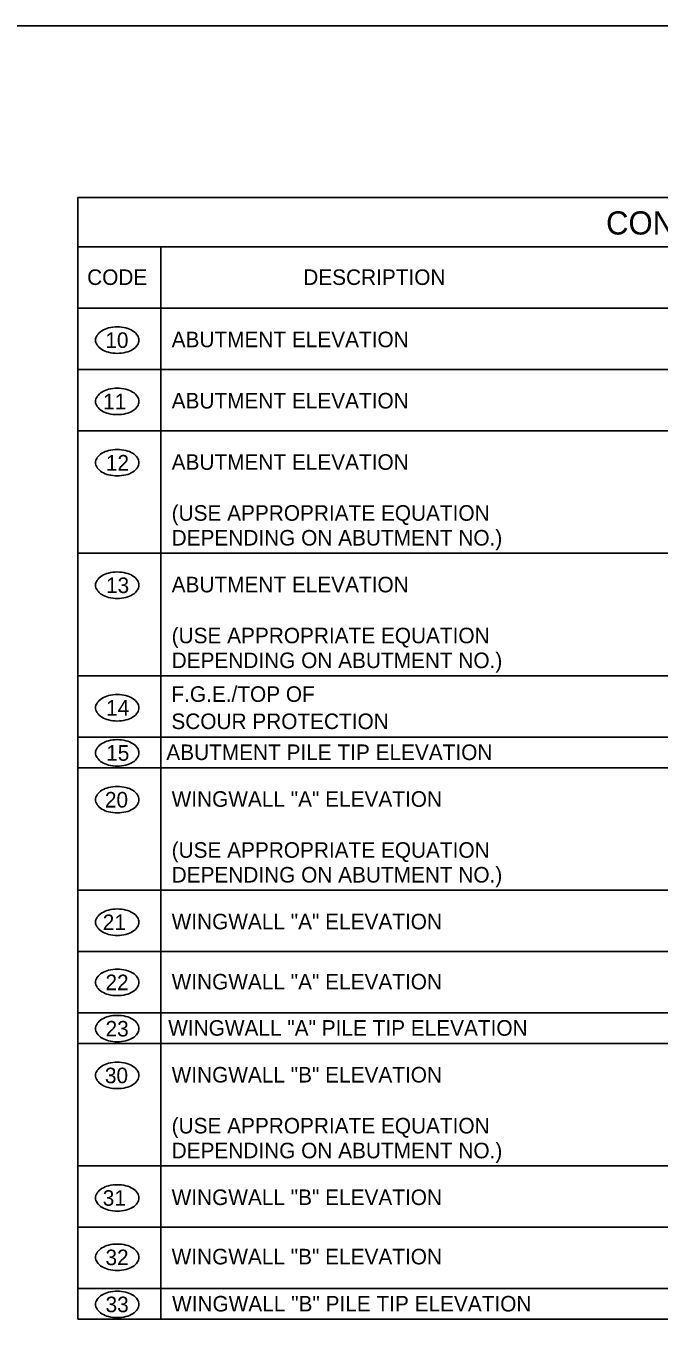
# Model space of a CAD drawing. Extents: x -5022 to -159, y 1126 to 7226.
# Drawn here: x -839.3 to -717.2, y 2049.8 to 2299.1 of the extents above; entities that cross this region are included whole.
import ezdxf

# ---------------------------------------------------------------- set-up
doc = ezdxf.new("R2010")
doc.units = 0
for name, color, linetype in [('2', 7, 'Continuous'), ('3', 7, 'Continuous'), ('5', 7, 'Continuous')]:
    doc.layers.add(name, color=color, linetype=linetype)

msp = doc.modelspace()

# ---------------------------------------------------------------- linework, layer by layer
at = {"layer": '2'}
msp.add_line((-491.13, 2299.14), (-1277.13, 2299.14), dxfattribs=at)
for centre, radius, start, end in [((-824.22, 2238.55), 1.61, 145.8704, 180), ((-822.99, 2237.72), 3.1, 121.4296, 145.8704), ((-822.18, 2236.39), 4.65, 104.2049, 121.4296), ((-821.65, 2234.29), 6.82, 90, 104.2049), ((-821.65, 2234.29), 6.82, 75.7951, 90), ((-821.11, 2236.39), 4.65, 58.5704, 75.7951), ((-820.3, 2237.72), 3.1, 34.1296, 58.5704), ((-819.07, 2238.55), 1.61, 0, 34.1296), ((-824.22, 2238.55), 1.61, 180, 214.1296), ((-822.99, 2239.39), 3.1, 214.1296, 238.5704), ((-822.18, 2240.72), 4.65, 238.5704, 255.7951), ((-821.11, 2240.72), 4.65, 284.2049, 301.4296), ((-820.3, 2239.39), 3.1, 301.4296, 325.8704), ((-819.07, 2238.55), 1.61, 325.8704, 0), ((-821.65, 2242.82), 6.82, 255.7951, 270), ((-821.65, 2242.82), 6.82, 270, 284.2049), ((-822.18, 2224.58), 4.65, 104.2049, 121.4296), ((-821.65, 2222.48), 6.82, 90, 104.2049), ((-821.65, 2222.48), 6.82, 75.7951, 90), ((-821.11, 2224.58), 4.65, 58.5704, 75.7951), ((-824.22, 2226.74), 1.61, 145.8704, 180), ((-824.22, 2226.74), 1.61, 180, 214.1296), ((-822.99, 2225.91), 3.1, 121.4296, 145.8704), ((-820.3, 2225.91), 3.1, 34.1296, 58.5704), ((-819.07, 2226.74), 1.61, 0, 34.1296), ((-819.07, 2226.74), 1.61, 325.8704, 0), ((-822.99, 2227.58), 3.1, 214.1296, 238.5704), ((-822.18, 2228.9), 4.65, 238.5704, 255.7951), ((-821.65, 2231.01), 6.82, 255.7951, 270), ((-821.65, 2231.01), 6.82, 270, 284.2049), ((-821.11, 2228.9), 4.65, 284.2049, 301.4296), ((-820.3, 2227.58), 3.1, 301.4296, 325.8704), ((-822.99, 2214.1), 3.1, 121.4296, 145.8704), ((-822.18, 2212.77), 4.65, 104.2049, 121.4296), ((-821.65, 2210.66), 6.82, 90, 104.2049), ((-821.65, 2210.66), 6.82, 75.7951, 90), ((-821.11, 2212.77), 4.65, 58.5704, 75.7951), ((-820.3, 2214.1), 3.1, 34.1296, 58.5704), ((-824.22, 2214.93), 1.61, 145.8704, 180), ((-824.22, 2214.93), 1.61, 180, 214.1296), ((-822.99, 2215.77), 3.1, 214.1296, 238.5704), ((-820.3, 2215.77), 3.1, 301.4296, 325.8704), ((-819.07, 2214.93), 1.61, 0, 34.1296), ((-819.07, 2214.93), 1.61, 325.8704, 0), ((-822.18, 2217.09), 4.65, 238.5704, 255.7951), ((-821.65, 2219.2), 6.82, 255.7951, 270), ((-821.65, 2219.2), 6.82, 270, 284.2049), ((-821.11, 2217.09), 4.65, 284.2049, 301.4296), ((-821.65, 2187.04), 6.82, 90, 104.2049), ((-821.65, 2187.04), 6.82, 75.7951, 90), ((-824.22, 2191.31), 1.61, 145.8704, 180), ((-822.99, 2190.48), 3.1, 121.4296, 145.8704), ((-822.18, 2189.15), 4.65, 104.2049, 121.4296), ((-821.11, 2189.15), 4.65, 58.5704, 75.7951), ((-820.3, 2190.48), 3.1, 34.1296, 58.5704), ((-819.07, 2191.31), 1.61, 0, 34.1296), ((-824.22, 2191.31), 1.61, 180, 214.1296), ((-822.99, 2192.14), 3.1, 214.1296, 238.5704), ((-822.18, 2193.47), 4.65, 238.5704, 255.7951), ((-821.65, 2195.58), 6.82, 255.7951, 270), ((-821.65, 2195.58), 6.82, 270, 284.2049), ((-821.11, 2193.47), 4.65, 284.2049, 301.4296), ((-820.3, 2192.14), 3.1, 301.4296, 325.8704), ((-819.07, 2191.31), 1.61, 325.8704, 0), ((-822.99, 2166.85), 3.1, 121.4296, 145.8704), ((-822.18, 2165.52), 4.65, 104.2049, 121.4296), ((-821.65, 2163.42), 6.82, 90, 104.2049), ((-821.65, 2163.42), 6.82, 75.7951, 90), ((-821.11, 2165.52), 4.65, 58.5704, 75.7951), ((-820.3, 2166.85), 3.1, 34.1296, 58.5704), ((-824.22, 2167.69), 1.61, 145.8704, 180), ((-824.22, 2167.69), 1.61, 180, 214.1296), ((-822.99, 2168.52), 3.1, 214.1296, 238.5704), ((-820.3, 2168.52), 3.1, 301.4296, 325.8704), ((-819.07, 2167.69), 1.61, 0, 34.1296), ((-819.07, 2167.69), 1.61, 325.8704, 0), ((-822.18, 2169.85), 4.65, 238.5704, 255.7951), ((-821.65, 2171.95), 6.82, 255.7951, 270), ((-821.65, 2171.95), 6.82, 270, 284.2049), ((-821.11, 2169.85), 4.65, 284.2049, 301.4296), ((-821.65, 2154.72), 6.82, 90, 104.2049), ((-821.65, 2154.72), 6.82, 75.7951, 90), ((-824.22, 2158.99), 1.61, 145.8704, 180), ((-824.22, 2158.99), 1.61, 180, 214.1296), ((-822.99, 2158.15), 3.1, 121.4296, 145.8704), ((-822.18, 2156.82), 4.65, 104.2049, 121.4296), ((-821.11, 2156.82), 4.65, 58.5704, 75.7951), ((-820.3, 2158.15), 3.1, 34.1296, 58.5704), ((-819.07, 2158.99), 1.61, 0, 34.1296), ((-819.07, 2158.99), 1.61, 325.8704, 0), ((-822.99, 2159.82), 3.1, 214.1296, 238.5704), ((-822.18, 2161.15), 4.65, 238.5704, 255.7951), ((-821.65, 2163.25), 6.82, 255.7951, 270), ((-821.65, 2163.25), 6.82, 270, 284.2049), ((-821.11, 2161.15), 4.65, 284.2049, 301.4296), ((-820.3, 2159.82), 3.1, 301.4296, 325.8704), ((-822.99, 2149.14), 3.1, 121.4296, 145.8704), ((-822.18, 2147.81), 4.65, 104.2049, 121.4296), ((-821.65, 2145.7), 6.82, 90, 104.2049), ((-821.65, 2145.7), 6.82, 75.7951, 90), ((-821.11, 2147.81), 4.65, 58.5704, 75.7951), ((-820.3, 2149.14), 3.1, 34.1296, 58.5704), ((-824.22, 2149.97), 1.61, 145.8704, 180), ((-824.22, 2149.97), 1.61, 180, 214.1296), ((-822.99, 2150.8), 3.1, 214.1296, 238.5704), ((-820.3, 2150.8), 3.1, 301.4296, 325.8704), ((-819.07, 2149.97), 1.61, 0, 34.1296), ((-819.07, 2149.97), 1.61, 325.8704, 0), ((-822.18, 2152.13), 4.65, 238.5704, 255.7951), ((-821.65, 2154.24), 6.82, 255.7951, 270), ((-821.65, 2154.24), 6.82, 270, 284.2049), ((-821.11, 2152.13), 4.65, 284.2049, 301.4296), ((-824.22, 2126.35), 1.61, 145.8704, 180), ((-822.99, 2125.51), 3.1, 121.4296, 145.8704), ((-822.18, 2124.18), 4.65, 104.2049, 121.4296), ((-821.65, 2122.08), 6.82, 90, 104.2049), ((-821.65, 2122.08), 6.82, 75.7951, 90), ((-821.11, 2124.18), 4.65, 58.5704, 75.7951), ((-820.3, 2125.51), 3.1, 34.1296, 58.5704), ((-819.07, 2126.35), 1.61, 0, 34.1296), ((-824.22, 2126.35), 1.61, 180, 214.1296), ((-822.99, 2127.18), 3.1, 214.1296, 238.5704), ((-822.18, 2128.51), 4.65, 238.5704, 255.7951), ((-821.11, 2128.51), 4.65, 284.2049, 301.4296), ((-820.3, 2127.18), 3.1, 301.4296, 325.8704), ((-819.07, 2126.35), 1.61, 325.8704, 0), ((-821.65, 2130.61), 6.82, 255.7951, 270), ((-821.65, 2130.61), 6.82, 270, 284.2049), ((-822.99, 2113.92), 3.1, 121.4296, 145.8704), ((-822.18, 2112.59), 4.65, 104.2049, 121.4296), ((-821.65, 2110.49), 6.82, 90, 104.2049), ((-821.65, 2110.49), 6.82, 75.7951, 90), ((-821.11, 2112.59), 4.65, 58.5704, 75.7951), ((-820.3, 2113.92), 3.1, 34.1296, 58.5704), ((-824.22, 2114.76), 1.61, 145.8704, 180), ((-824.22, 2114.76), 1.61, 180, 214.1296), ((-819.07, 2114.76), 1.61, 0, 34.1296), ((-819.07, 2114.76), 1.61, 325.8704, 0), ((-822.99, 2115.59), 3.1, 214.1296, 238.5704), ((-822.18, 2116.92), 4.65, 238.5704, 255.7951), ((-821.65, 2119.02), 6.82, 255.7951, 270), ((-821.65, 2119.02), 6.82, 270, 284.2049), ((-821.11, 2116.92), 4.65, 284.2049, 301.4296), ((-820.3, 2115.59), 3.1, 301.4296, 325.8704), ((-824.22, 2105.83), 1.61, 145.8704, 180), ((-822.99, 2105), 3.1, 121.4296, 145.8704), ((-822.18, 2103.67), 4.65, 104.2049, 121.4296), ((-821.65, 2101.57), 6.82, 90, 104.2049), ((-821.65, 2101.57), 6.82, 75.7951, 90), ((-821.11, 2103.67), 4.65, 58.5704, 75.7951), ((-820.3, 2105), 3.1, 34.1296, 58.5704), ((-819.07, 2105.83), 1.61, 0, 34.1296), ((-824.22, 2105.83), 1.61, 180, 214.1296), ((-822.99, 2106.67), 3.1, 214.1296, 238.5704), ((-820.3, 2106.67), 3.1, 301.4296, 325.8704), ((-819.07, 2105.83), 1.61, 325.8704, 0), ((-822.18, 2108), 4.65, 238.5704, 255.7951), ((-821.65, 2110.1), 6.82, 255.7951, 270), ((-821.65, 2110.1), 6.82, 270, 284.2049), ((-821.11, 2108), 4.65, 284.2049, 301.4296), ((-822.18, 2094.66), 4.65, 104.2049, 121.4296), ((-821.65, 2092.55), 6.82, 90, 104.2049), ((-821.65, 2092.55), 6.82, 75.7951, 90), ((-821.11, 2094.66), 4.65, 58.5704, 75.7951), ((-824.22, 2096.82), 1.61, 145.8704, 180), ((-824.22, 2096.82), 1.61, 180, 214.1296), ((-822.99, 2095.98), 3.1, 121.4296, 145.8704), ((-820.3, 2095.98), 3.1, 34.1296, 58.5704), ((-819.07, 2096.82), 1.61, 0, 34.1296), ((-819.07, 2096.82), 1.61, 325.8704, 0), ((-822.99, 2097.65), 3.1, 214.1296, 238.5704), ((-822.18, 2098.98), 4.65, 238.5704, 255.7951), ((-821.65, 2101.09), 6.82, 255.7951, 270), ((-821.65, 2101.09), 6.82, 270, 284.2049), ((-821.11, 2098.98), 4.65, 284.2049, 301.4296), ((-820.3, 2097.65), 3.1, 301.4296, 325.8704), ((-822.99, 2072.36), 3.1, 121.4296, 145.8704), ((-822.18, 2071.03), 4.65, 104.2049, 121.4296), ((-821.65, 2068.93), 6.82, 90, 104.2049), ((-821.65, 2068.93), 6.82, 75.7951, 90), ((-821.11, 2071.03), 4.65, 58.5704, 75.7951), ((-820.3, 2072.36), 3.1, 34.1296, 58.5704), ((-824.22, 2073.2), 1.61, 145.8704, 180), ((-824.22, 2073.2), 1.61, 180, 214.1296), ((-822.99, 2074.03), 3.1, 214.1296, 238.5704), ((-820.3, 2074.03), 3.1, 301.4296, 325.8704), ((-819.07, 2073.2), 1.61, 0, 34.1296), ((-819.07, 2073.2), 1.61, 325.8704, 0), ((-822.18, 2075.36), 4.65, 238.5704, 255.7951), ((-821.65, 2077.46), 6.82, 255.7951, 270), ((-821.65, 2077.46), 6.82, 270, 284.2049), ((-821.11, 2075.36), 4.65, 284.2049, 301.4296), ((-821.65, 2057.49), 6.82, 90, 104.2049), ((-821.65, 2057.49), 6.82, 75.7951, 90), ((-824.22, 2061.76), 1.61, 145.8704, 180), ((-824.22, 2061.76), 1.61, 180, 214.1296), ((-822.99, 2060.92), 3.1, 121.4296, 145.8704), ((-822.18, 2059.59), 4.65, 104.2049, 121.4296), ((-821.11, 2059.59), 4.65, 58.5704, 75.7951), ((-820.3, 2060.92), 3.1, 34.1296, 58.5704), ((-819.07, 2061.76), 1.61, 0, 34.1296), ((-819.07, 2061.76), 1.61, 325.8704, 0), ((-822.99, 2062.59), 3.1, 214.1296, 238.5704), ((-822.18, 2063.92), 4.65, 238.5704, 255.7951), ((-821.65, 2066.02), 6.82, 255.7951, 270), ((-821.65, 2066.02), 6.82, 270, 284.2049), ((-821.11, 2063.92), 4.65, 284.2049, 301.4296), ((-820.3, 2062.59), 3.1, 301.4296, 325.8704), ((-822.99, 2051.85), 3.1, 121.4296, 145.8704), ((-822.18, 2050.52), 4.65, 104.2049, 121.4296), ((-821.65, 2048.42), 6.82, 90, 104.2049), ((-821.65, 2048.42), 6.82, 75.7951, 90), ((-821.11, 2050.52), 4.65, 58.5704, 75.7951), ((-820.3, 2051.85), 3.1, 34.1296, 58.5704), ((-824.22, 2052.68), 1.61, 145.8704, 180), ((-824.22, 2052.68), 1.61, 180, 214.1296), ((-822.99, 2053.52), 3.1, 214.1296, 238.5704), ((-820.3, 2053.52), 3.1, 301.4296, 325.8704), ((-819.07, 2052.68), 1.61, 0, 34.1296), ((-819.07, 2052.68), 1.61, 325.8704, 0), ((-822.18, 2054.84), 4.65, 238.5704, 255.7951), ((-821.65, 2056.95), 6.82, 255.7951, 270), ((-821.65, 2056.95), 6.82, 270, 284.2049), ((-821.11, 2054.84), 4.65, 284.2049, 301.4296)]:
    msp.add_arc(centre, radius, start, end, dxfattribs=at)
at = {"layer": '5'}
for p, q in [((-829.23, 2266.08), (-829.23, 2049.84)), ((-829.23, 2266.08), (-499.07, 2266.08)), ((-829.23, 2256.54), (-499.07, 2256.54)), ((-813.28, 2256.54), (-813.28, 2049.84)), ((-829.23, 2244.72), (-499.07, 2244.72)), ((-829.23, 2232.91), (-499.07, 2232.91)), ((-829.23, 2221.1), (-499.07, 2221.1)), ((-829.23, 2197.48), (-499.07, 2197.48)), ((-829.23, 2173.86), (-499.07, 2173.86)), ((-829.23, 2162.04), (-499.07, 2162.04)), ((-829.23, 2156.14), (-499.07, 2156.14)), ((-829.23, 2132.52), (-499.07, 2132.52)), ((-829.23, 2120.71), (-499.07, 2120.71)), ((-829.23, 2108.89), (-499.07, 2108.89)), ((-829.23, 2102.99), (-499.07, 2102.99)), ((-829.23, 2079.37), (-499.07, 2079.37)), ((-829.23, 2067.55), (-499.07, 2067.55)), ((-829.23, 2055.74), (-499.07, 2055.74)), ((-829.23, 2049.84), (-499.07, 2049.84))]:
    msp.add_line(p, q, dxfattribs=at)

# ---------------------------------------------------------------- texts
at = {"layer": '2'}
for s, height, p in [('CONTROL STATIONS AND ELEVATIONS', 4.4793, (-727.41, 2258.91)), ('CODE', 3, (-827.45, 2249.19)), ('DESCRIPTION', 3.0001, (-785.79, 2249.19)), ('10', 3, (-823.95, 2237.05)), ('ABUTMENT ELEVATION', 3.0001, (-811.16, 2237.19)), ('11', 3, (-824.37, 2225.23)), ('ABUTMENT ELEVATION', 3.0001, (-811.16, 2225.38)), ('12', 3, (-823.84, 2213.42)), ('ABUTMENT ELEVATION', 3.0001, (-811.16, 2213.56)), ('(USE APPROPRIATE EQUATION', 3.0001, (-811.16, 2203.74)), ('DEPENDING ON ABUTMENT NO.)', 3.0001, (-811.16, 2198.96)), ('13', 3, (-823.82, 2189.8)), ('ABUTMENT ELEVATION', 3.0001, (-811.16, 2189.94)), ('(USE APPROPRIATE EQUATION', 3.0001, (-811.16, 2180.12)), ('DEPENDING ON ABUTMENT NO.)', 3.0001, (-811.16, 2175.33)), ('14', 3, (-823.81, 2166.18)), ('15', 3, (-823.78, 2157.48)), ('ABUTMENT PILE TIP ELEVATION', 3.0001, (-812.19, 2157.61)), ('20', 3, (-824.03, 2148.46)), ('WINGWALL "A" ELEVATION', 3.0001, (-811.16, 2148.6)), ('(USE APPROPRIATE EQUATION', 3.0001, (-811.16, 2138.77)), ('DEPENDING ON ABUTMENT NO.)', 3.0001, (-811.16, 2134)), ('21', 3, (-824.45, 2124.84)), ('WINGWALL "A" ELEVATION', 3.0001, (-811.16, 2124.98)), ('22', 3, (-823.92, 2113.25)), ('WINGWALL "A" ELEVATION', 3.0001, (-811.16, 2113.39)), ('23', 3, (-823.9, 2104.32)), ('WINGWALL "A" PILE TIP ELEVATION', 3.0001, (-811.82, 2104.47)), ('30', 3, (-824.03, 2095.31)), ('WINGWALL "B" ELEVATION', 3.0001, (-811.16, 2095.45)), ('(USE APPROPRIATE EQUATION', 3.0001, (-811.16, 2085.63)), ('DEPENDING ON ABUTMENT NO.)', 3.0001, (-811.16, 2080.84)), ('31', 3, (-824.45, 2071.69)), ('WINGWALL "B" ELEVATION', 3.0001, (-811.16, 2071.83)), ('32', 3, (-823.92, 2060.24)), ('WINGWALL "B" ELEVATION', 3.0001, (-811.16, 2060.39)), ('WINGWALL "B" PILE TIP ELEVATION', 3.0001, (-811.08, 2051.31)), ('33', 3, (-823.9, 2051.17))]:
    msp.add_text(s, height=height, dxfattribs=at).set_placement(p)
at = {"layer": '3'}
for s, p in [('F.G.E./TOP OF', (-811.21, 2168.83)), ('SCOUR PROTECTION', (-811.21, 2163.58))]:
    msp.add_text(s, height=2.9998, dxfattribs=at).set_placement(p)

doc.saveas('drawing.dxf')
